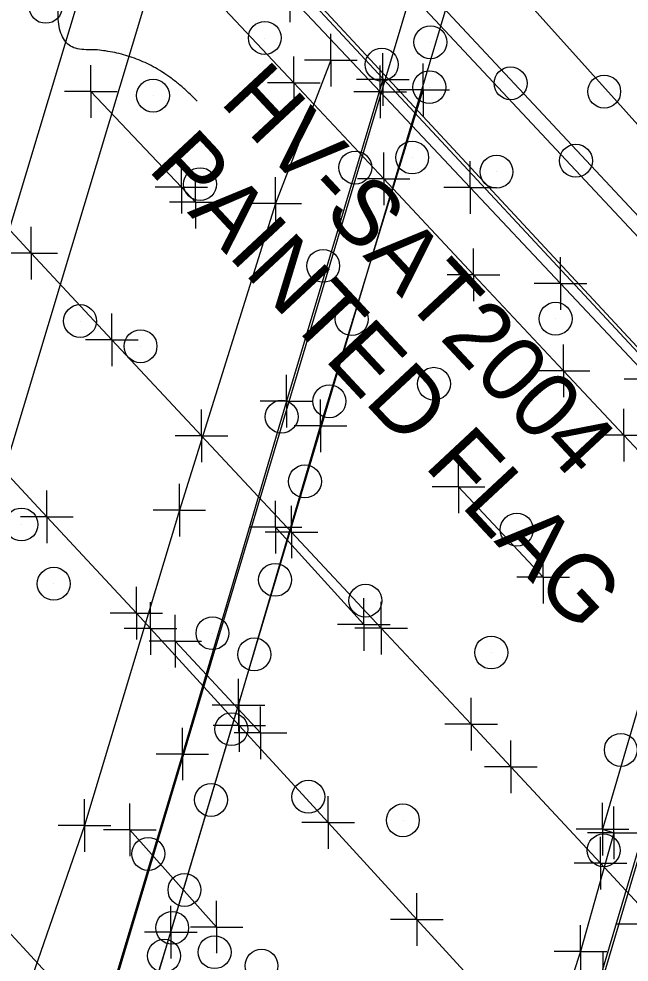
# Model space of a CAD drawing. Extents: x 0 to 1944463, y 0 to 420651.
# Drawn here: x 1943164.5 to 1943210.9, y 417466.5 to 417538.1 of the extents above; entities that cross this region are included whole.
import ezdxf

# ---------------------------------------------------------------- set-up
doc = ezdxf.new("R2010")
doc.units = 0
for name, color, linetype in [('AERIAL - CTRL - Text', 7, 'Continuous'), ('SUR - DRG - Bridge Deck', 7, 'Continuous'), ('SUR - DRG - Bridges', 7, 'Continuous'), ('SUR - DTM - Breaklines', 7, 'Continuous'), ('SUR - DTM - Breaklines - Points - Locators', 7, 'Continuous'), ('SUR - DTM - Spot Points - Locators', 7, 'Continuous'), ('SUR - TR-CTRL - Pavement Marking', 7, 'Continuous'), ('SUR - TR-CTRL - Pavement Marking - Points - Locators', 7, 'Continuous'), ('SUR - TRAN - Features', 7, 'Continuous'), ('SUR - TRAN - Railroads', 7, 'Continuous'), ('SUR - VEG - Features', 7, 'Continuous')]:
    doc.layers.add(name, color=color, linetype=linetype)

msp = doc.modelspace()

# ---------------------------------------------------------------- linework, layer by layer
at = {"layer": 'AERIAL - CTRL - Text'}
msp.add_open_spline([(1943178.089, 417531.873), (1943174.395, 417535.811), (1943164.646, 417535.811), (1943171.644, 417552.023)], degree=2, dxfattribs=at)
at = {"layer": 'SUR - DRG - Bridge Deck'}
for points in [[(1943115.55, 417624.338), (1943152.054, 417585.354), (1943187.334, 417547.54), (1943222.006, 417510.484)], [(1943113.605, 417617.591), (1943147.37, 417581.35), (1943183.041, 417543.482), (1943220.131, 417503.654)], [(1943113.608, 417617.795), (1943147.49, 417581.399), (1943183.285, 417543.641), (1943220.171, 417503.952)]]:
    msp.add_lwpolyline(points, dxfattribs=at)
at = {"layer": 'SUR - DRG - Bridges'}
msp.add_line((1943166.44, 417446.69), (1943194.62, 417540.97), dxfattribs=at)
msp.add_lwpolyline([(1943194.586, 417417.65), (1943160.612, 417454.166), (1943126.96, 417490.097), (1943087.359, 417532.419), (1943088.24, 417533.281), (1943102.062, 417579.551), (1943115.41, 417624.415), (1943114.938, 417624.906), (1943115.852, 417625.619), (1943152.828, 417586.155), (1943187.702, 417548.755), (1943222.943, 417511.078), (1943222.064, 417510.2)], close=True, dxfattribs=at)
msp.add_lwpolyline([(1943166.44, 417446.69), (1943169.26, 417445.81), (1943197.39, 417540.17), (1943194.62, 417540.97)], dxfattribs=at)
at = {"layer": 'SUR - DTM - Breaklines'}
for points in [[(1943188.25, 417535), (1943184.04, 417524.1), (1943176.74, 417500.81), (1943169.52, 417476.85), (1943165.09, 417464.05)], [(1943192.22, 417533.53), (1943184.89, 417509.08), (1943176.97, 417482.28), (1943169.11, 417456.04), (1943165.69, 417446.3)], [(1943169.06, 417445.88), (1943170.3, 417449.24), (1943172.17, 417455.81), (1943173.54, 417460.42), (1943176.1, 417468.74), (1943181.24, 417486), (1943187.47, 417507.21), (1943195.29, 417532.75)], [(1943218.59, 417509.53), (1943215.96, 417501.29), (1943213.27, 417491.41), (1943208.92, 417476.57), (1943209.78, 417476.3), (1943207.25, 417467.28), (1943203.9, 417457.1), (1943201.6, 417449.06), (1943199.15, 417440.38), (1943194, 417424.62), (1943191.92, 417417.37)], [(1943197.33, 417425.5), (1943208.97, 417465.3), (1943220.33, 417503.55)]]:
    msp.add_lwpolyline(points, dxfattribs=at)
at = {"layer": 'SUR - DTM - Breaklines - Points - Locators'}
for p, q in [((1943188.25, 417535), (1943188.25, 417537)), ((1943192.22, 417533.53), (1943192.22, 417535.53)), ((1943188.25, 417535), (1943186.25, 417535)), ((1943188.25, 417535), (1943190.25, 417535)), ((1943188.25, 417535), (1943188.25, 417533)), ((1943195.29, 417532.75), (1943195.29, 417534.75)), ((1943192.22, 417533.53), (1943190.22, 417533.53)), ((1943192.22, 417533.53), (1943194.22, 417533.53)), ((1943192.22, 417533.53), (1943192.22, 417531.53)), ((1943195.29, 417532.75), (1943193.29, 417532.75)), ((1943195.29, 417532.75), (1943197.29, 417532.75)), ((1943195.29, 417532.75), (1943195.29, 417530.75)), ((1943184.04, 417524.1), (1943184.04, 417526.1)), ((1943184.04, 417524.1), (1943182.04, 417524.1)), ((1943184.04, 417524.1), (1943186.04, 417524.1)), ((1943184.04, 417524.1), (1943184.04, 417522.1)), ((1943184.89, 417509.08), (1943184.89, 417511.08)), ((1943184.89, 417509.08), (1943182.89, 417509.08)), ((1943184.89, 417509.08), (1943186.89, 417509.08)), ((1943184.89, 417509.08), (1943184.89, 417507.08)), ((1943187.47, 417507.21), (1943187.47, 417509.21)), ((1943187.47, 417507.21), (1943185.47, 417507.21)), ((1943187.47, 417507.21), (1943189.47, 417507.21)), ((1943187.47, 417507.21), (1943187.47, 417505.21)), ((1943176.74, 417500.81), (1943176.74, 417502.81)), ((1943176.74, 417500.81), (1943174.74, 417500.81)), ((1943176.74, 417500.81), (1943178.74, 417500.81)), ((1943176.74, 417500.81), (1943176.74, 417498.81)), ((1943181.24, 417486), (1943181.24, 417488)), ((1943181.24, 417486), (1943179.24, 417486)), ((1943181.24, 417486), (1943183.24, 417486)), ((1943181.24, 417486), (1943181.24, 417484)), ((1943176.97, 417482.28), (1943176.97, 417484.28)), ((1943176.97, 417482.28), (1943174.97, 417482.28)), ((1943176.97, 417482.28), (1943178.97, 417482.28)), ((1943176.97, 417482.28), (1943176.97, 417480.28)), ((1943169.52, 417476.85), (1943169.52, 417478.85)), ((1943208.92, 417476.57), (1943208.92, 417478.57)), ((1943209.78, 417476.3), (1943209.78, 417478.3)), ((1943169.52, 417476.85), (1943167.52, 417476.85)), ((1943169.52, 417476.85), (1943171.52, 417476.85)), ((1943169.52, 417476.85), (1943169.52, 417474.85)), ((1943208.92, 417476.57), (1943206.92, 417476.57)), ((1943208.92, 417476.57), (1943210.92, 417476.57)), ((1943208.92, 417476.57), (1943208.92, 417474.57)), ((1943209.78, 417476.3), (1943207.78, 417476.3)), ((1943209.78, 417476.3), (1943211.78, 417476.3)), ((1943209.78, 417476.3), (1943209.78, 417474.3)), ((1943176.1, 417468.74), (1943176.1, 417470.74)), ((1943207.25, 417467.28), (1943207.25, 417469.28)), ((1943176.1, 417468.74), (1943174.1, 417468.74)), ((1943176.1, 417468.74), (1943178.1, 417468.74)), ((1943176.1, 417468.74), (1943176.1, 417466.74)), ((1943207.25, 417467.28), (1943205.25, 417467.28)), ((1943207.25, 417467.28), (1943209.25, 417467.28)), ((1943207.25, 417467.28), (1943207.25, 417465.28)), ((1943208.97, 417465.3), (1943208.97, 417467.3))]:
    msp.add_line(p, q, dxfattribs=at)
at = {"layer": 'SUR - DTM - Spot Points - Locators'}
for p, q in [((1943183.25, 417536.68), (1943183.25, 417536.68)), ((1943195.84, 417536.35), (1943195.84, 417536.35)), ((1943192.14, 417534.65), (1943192.14, 417534.65)), ((1943201.94, 417533.23), (1943201.94, 417533.23)), ((1943174.75, 417532.3), (1943174.75, 417532.3)), ((1943195.76, 417532.94), (1943195.76, 417532.94)), ((1943209.06, 417532.6), (1943209.06, 417532.6)), ((1943194.46, 417527.59), (1943194.46, 417527.59)), ((1943206.91, 417527.35), (1943206.91, 417527.35)), ((1943190.13, 417526.83), (1943190.13, 417526.83)), ((1943200.87, 417526.51), (1943200.87, 417526.51)), ((1943178.33, 417525.57), (1943178.33, 417525.57)), ((1943187.69, 417519.36), (1943187.69, 417519.36)), ((1943169.2, 417515.17), (1943169.2, 417515.17)), ((1943189.86, 417515.31), (1943189.86, 417515.31)), ((1943205.36, 417515.34), (1943205.36, 417515.34)), ((1943173.8, 417513.25), (1943173.8, 417513.25)), ((1943196.11, 417510.4), (1943196.11, 417510.4)), ((1943188.16, 417509.07), (1943188.16, 417509.07)), ((1943184.53, 417507.9), (1943184.53, 417507.9)), ((1943186.3, 417502.98), (1943186.3, 417502.98)), ((1943164.74, 417499.71), (1943164.74, 417499.71)), ((1943202.41, 417499.32), (1943202.41, 417499.32)), ((1943167.2, 417495.21), (1943167.2, 417495.21)), ((1943184.03, 417495.5), (1943184.03, 417495.5)), ((1943190.9, 417493.92), (1943190.9, 417493.92)), ((1943179.27, 417491.45), (1943179.27, 417491.45)), ((1943200.47, 417489.98), (1943200.47, 417489.98)), ((1943182.45, 417489.84), (1943182.45, 417489.84)), ((1943180.71, 417484.16), (1943180.71, 417484.16)), ((1943210.32, 417482.58), (1943210.32, 417482.58)), ((1943179.16, 417478.78), (1943179.16, 417478.78)), ((1943186.56, 417479.02), (1943186.56, 417479.02)), ((1943193.75, 417477.23), (1943193.75, 417477.23)), ((1943209.01, 417474.95), (1943209.01, 417474.95)), ((1943174.39, 417474.68), (1943174.39, 417474.68)), ((1943177.14, 417471.94), (1943177.14, 417471.94)), ((1943176.21, 417469.06), (1943176.21, 417469.06)), ((1943179.43, 417467.21), (1943179.43, 417467.21)), ((1943175.59, 417466.94), (1943175.59, 417466.94))]:
    msp.add_line(p, q, dxfattribs=at)
for centre in [(1943166.579, 417539.051), (1943183.239, 417536.691), (1943195.829, 417536.361), (1943192.129, 417534.661), (1943201.929, 417533.241), (1943195.749, 417532.951), (1943209.049, 417532.611), (1943174.739, 417532.311), (1943194.449, 417527.601), (1943190.119, 417526.841), (1943206.899, 417527.361), (1943200.859, 417526.521), (1943178.319, 417525.581), (1943187.679, 417519.371), (1943189.849, 417515.321), (1943205.349, 417515.351), (1943169.189, 417515.181), (1943173.789, 417513.261), (1943196.099, 417510.411), (1943188.149, 417509.081), (1943184.519, 417507.911), (1943186.289, 417502.991), (1943164.729, 417499.721), (1943202.399, 417499.331), (1943167.189, 417495.221), (1943184.019, 417495.511), (1943190.889, 417493.931), (1943179.259, 417491.461), (1943182.439, 417489.851), (1943200.459, 417489.991), (1943180.699, 417484.171), (1943210.309, 417482.591), (1943179.149, 417478.791), (1943186.549, 417479.031), (1943193.739, 417477.241), (1943174.379, 417474.691), (1943208.999, 417474.961), (1943177.129, 417471.951), (1943176.199, 417469.071), (1943179.419, 417467.221), (1943175.579, 417466.951), (1943182.989, 417466.191)]:
    msp.add_circle(centre, 1.25, dxfattribs=at)
at = {"layer": 'SUR - TR-CTRL - Pavement Marking'}
for points in [[(1943098.42, 417635.279), (1943103.018, 417629.276), (1943109.491, 417621.654), (1943112.594, 417618), (1943119.388, 417610.663), (1943126.183, 417603.326), (1943132.978, 417595.989), (1943138.955, 417589.534), (1943145.75, 417582.197), (1943152.545, 417574.86), (1943159.34, 417567.523), (1943166.134, 417560.186), (1943171.446, 417554.451), (1943178.3, 417547.169), (1943185.154, 417539.887), (1943192.008, 417532.606), (1943198.862, 417525.324), (1943205.716, 417518.042), (1943212.57, 417510.76)], [(1943109.726, 417614.439), (1943116.557, 417607.135), (1943123.387, 417599.832), (1943130.218, 417592.529), (1943137.049, 417585.225), (1943142.549, 417579.345), (1943149.353, 417572.016), (1943156.157, 417564.688), (1943162.961, 417557.359), (1943169.765, 417550.031), (1943171.766, 417547.876), (1943178.604, 417540.579), (1943185.442, 417533.282), (1943192.28, 417525.986), (1943199.118, 417518.689), (1943205.956, 417511.392), (1943210.536, 417506.506), (1943217.374, 417499.209)], [(1943049.034, 417591.82), (1943055.909, 417584.558), (1943062.785, 417577.297), (1943067.272, 417572.558), (1943074.12, 417565.271), (1943080.969, 417557.985), (1943087.818, 417550.698), (1943089.003, 417549.436), (1943095.803, 417542.105), (1943102.604, 417534.773), (1943109.404, 417527.441), (1943116.204, 417520.109), (1943117.838, 417518.348), (1943124.638, 417511.016), (1943131.439, 417503.684), (1943138.239, 417496.352), (1943145.039, 417489.02), (1943147.729, 417486.12), (1943154.51, 417478.77), (1943161.291, 417471.42), (1943168.072, 417464.071)], [(1943109.208, 417580.822), (1943116.02, 417573.5), (1943122.831, 417566.179), (1943129.643, 417558.857), (1943136.454, 417551.536), (1943138.234, 417549.623), (1943145.045, 417542.301), (1943151.857, 417534.98), (1943158.668, 417527.659), (1943165.48, 417520.337), (1943171.602, 417513.757), (1943178.432, 417506.453), (1943185.262, 417499.149), (1943192.092, 417491.844), (1943198.922, 417484.54), (1943201.947, 417481.305), (1943208.757, 417473.982), (1943215.567, 417466.659)], [(1943092.328, 417580.219), (1943099.155, 417572.913), (1943105.446, 417566.18), (1943112.254, 417558.855), (1943119.061, 417551.53), (1943125.869, 417544.204), (1943132.676, 417536.879), (1943139.483, 417529.554), (1943146.241, 417522.283), (1943153.048, 417514.958), (1943159.856, 417507.633), (1943166.663, 417500.307), (1943173.47, 417492.982), (1943174.548, 417491.823), (1943181.301, 417484.447), (1943188.054, 417477.072), (1943194.807, 417469.696), (1943199.772, 417464.274)], [(1943170.02, 417532.617), (1943176.893, 417525.354), (1943177.981, 417524.205)], [(1943197.974, 417502.571), (1943204.403, 417495.722)], [(1943184.064, 417499.513), (1943190.778, 417492.129)], [(1943176.433, 417490.854), (1943182.909, 417483.879)], [(1943172.97, 417476.519), (1943179.577, 417469.135)]]:
    msp.add_lwpolyline(points, dxfattribs=at)
at = {"layer": 'SUR - TR-CTRL - Pavement Marking - Points - Locators'}
for p, q in [((1943185.154, 417539.887), (1943185.154, 417537.887)), ((1943170.02, 417532.617), (1943170.02, 417534.617)), ((1943192.008, 417532.606), (1943192.008, 417534.606)), ((1943170.02, 417532.617), (1943168.02, 417532.617)), ((1943170.02, 417532.617), (1943172.02, 417532.617)), ((1943170.02, 417532.617), (1943170.02, 417530.617)), ((1943192.008, 417532.606), (1943190.008, 417532.606)), ((1943192.008, 417532.606), (1943194.008, 417532.606)), ((1943192.008, 417532.606), (1943192.008, 417530.606)), ((1943176.893, 417525.354), (1943176.893, 417527.354)), ((1943198.862, 417525.324), (1943198.862, 417527.324)), ((1943177.981, 417524.205), (1943177.981, 417526.205)), ((1943176.893, 417525.354), (1943174.893, 417525.354)), ((1943176.893, 417525.354), (1943178.893, 417525.354)), ((1943176.893, 417525.354), (1943176.893, 417523.354)), ((1943198.862, 417525.324), (1943196.862, 417525.324)), ((1943198.862, 417525.324), (1943200.862, 417525.324)), ((1943198.862, 417525.324), (1943198.862, 417523.324)), ((1943177.981, 417524.205), (1943175.981, 417524.205)), ((1943177.981, 417524.205), (1943179.981, 417524.205)), ((1943177.981, 417524.205), (1943177.981, 417522.205)), ((1943165.48, 417520.337), (1943165.48, 417522.337)), ((1943165.48, 417520.337), (1943163.48, 417520.337)), ((1943165.48, 417520.337), (1943167.48, 417520.337)), ((1943165.48, 417520.337), (1943165.48, 417518.337)), ((1943205.716, 417518.042), (1943205.716, 417520.042)), ((1943205.716, 417518.042), (1943203.716, 417518.042)), ((1943205.716, 417518.042), (1943207.716, 417518.042)), ((1943205.716, 417518.042), (1943205.716, 417516.042)), ((1943171.602, 417513.757), (1943171.602, 417515.757)), ((1943171.602, 417513.757), (1943169.602, 417513.757)), ((1943171.602, 417513.757), (1943173.602, 417513.757)), ((1943171.602, 417513.757), (1943171.602, 417511.757)), ((1943212.57, 417510.76), (1943210.57, 417510.76)), ((1943178.432, 417506.453), (1943178.432, 417508.453)), ((1943178.432, 417506.453), (1943176.432, 417506.453)), ((1943178.432, 417506.453), (1943180.432, 417506.453)), ((1943178.432, 417506.453), (1943178.432, 417504.453)), ((1943197.974, 417502.571), (1943197.974, 417504.571)), ((1943166.663, 417500.307), (1943166.663, 417502.307)), ((1943197.974, 417502.571), (1943195.974, 417502.571)), ((1943197.974, 417502.571), (1943199.974, 417502.571)), ((1943197.974, 417502.571), (1943197.974, 417500.571)), ((1943184.064, 417499.513), (1943184.064, 417501.513)), ((1943185.262, 417499.149), (1943185.262, 417501.149)), ((1943166.663, 417500.307), (1943164.663, 417500.307)), ((1943166.663, 417500.307), (1943168.663, 417500.307)), ((1943166.663, 417500.307), (1943166.663, 417498.307)), ((1943184.064, 417499.513), (1943182.064, 417499.513)), ((1943184.064, 417499.513), (1943186.064, 417499.513)), ((1943184.064, 417499.513), (1943184.064, 417497.513)), ((1943185.262, 417499.149), (1943183.262, 417499.149)), ((1943185.262, 417499.149), (1943187.262, 417499.149)), ((1943185.262, 417499.149), (1943185.262, 417497.149)), ((1943204.403, 417495.722), (1943204.403, 417497.722)), ((1943204.403, 417495.722), (1943202.403, 417495.722)), ((1943204.403, 417495.722), (1943206.403, 417495.722)), ((1943204.403, 417495.722), (1943204.403, 417493.722)), ((1943173.47, 417492.982), (1943173.47, 417494.982)), ((1943174.548, 417491.823), (1943174.548, 417493.823)), ((1943190.778, 417492.129), (1943190.778, 417494.129)), ((1943192.092, 417491.844), (1943192.092, 417493.844)), ((1943173.47, 417492.982), (1943171.47, 417492.982)), ((1943173.47, 417492.982), (1943175.47, 417492.982)), ((1943173.47, 417492.982), (1943173.47, 417490.982)), ((1943176.433, 417490.854), (1943176.433, 417492.854)), ((1943190.778, 417492.129), (1943188.778, 417492.129)), ((1943190.778, 417492.129), (1943192.778, 417492.129)), ((1943190.778, 417492.129), (1943190.778, 417490.129)), ((1943174.548, 417491.823), (1943172.548, 417491.823)), ((1943174.548, 417491.823), (1943176.548, 417491.823)), ((1943174.548, 417491.823), (1943174.548, 417489.823)), ((1943192.092, 417491.844), (1943190.092, 417491.844)), ((1943192.092, 417491.844), (1943194.092, 417491.844)), ((1943192.092, 417491.844), (1943192.092, 417489.844)), ((1943176.433, 417490.854), (1943174.433, 417490.854)), ((1943176.433, 417490.854), (1943178.433, 417490.854)), ((1943176.433, 417490.854), (1943176.433, 417488.854)), ((1943181.301, 417484.447), (1943181.301, 417486.447)), ((1943198.922, 417484.54), (1943198.922, 417486.54)), ((1943182.909, 417483.879), (1943182.909, 417485.879)), ((1943181.301, 417484.447), (1943179.301, 417484.447)), ((1943181.301, 417484.447), (1943183.301, 417484.447)), ((1943181.301, 417484.447), (1943181.301, 417482.447)), ((1943198.922, 417484.54), (1943196.922, 417484.54)), ((1943198.922, 417484.54), (1943200.922, 417484.54)), ((1943198.922, 417484.54), (1943198.922, 417482.54)), ((1943182.909, 417483.879), (1943180.909, 417483.879)), ((1943182.909, 417483.879), (1943184.909, 417483.879)), ((1943182.909, 417483.879), (1943182.909, 417481.879)), ((1943201.947, 417481.305), (1943201.947, 417483.305)), ((1943201.947, 417481.305), (1943199.947, 417481.305)), ((1943201.947, 417481.305), (1943203.947, 417481.305)), ((1943201.947, 417481.305), (1943201.947, 417479.305)), ((1943172.97, 417476.519), (1943172.97, 417478.519)), ((1943188.054, 417477.072), (1943188.054, 417479.072)), ((1943188.054, 417477.072), (1943186.054, 417477.072)), ((1943188.054, 417477.072), (1943190.054, 417477.072)), ((1943188.054, 417477.072), (1943188.054, 417475.072)), ((1943172.97, 417476.519), (1943170.97, 417476.519)), ((1943172.97, 417476.519), (1943174.97, 417476.519)), ((1943172.97, 417476.519), (1943172.97, 417474.519)), ((1943208.757, 417473.982), (1943208.757, 417475.982)), ((1943208.757, 417473.982), (1943206.757, 417473.982)), ((1943208.757, 417473.982), (1943210.757, 417473.982)), ((1943208.757, 417473.982), (1943208.757, 417471.982)), ((1943194.807, 417469.696), (1943194.807, 417471.696)), ((1943179.577, 417469.135), (1943179.577, 417471.135)), ((1943194.807, 417469.696), (1943192.807, 417469.696)), ((1943194.807, 417469.696), (1943196.807, 417469.696)), ((1943194.807, 417469.696), (1943194.807, 417467.696)), ((1943211.927, 417469.354), (1943209.927, 417469.354)), ((1943179.577, 417469.135), (1943177.577, 417469.135)), ((1943179.577, 417469.135), (1943181.577, 417469.135)), ((1943179.577, 417469.135), (1943179.577, 417467.135))]:
    msp.add_line(p, q, dxfattribs=at)
at = {"layer": 'SUR - TRAN - Features'}
for p, q in [((1943185.442, 417533.282), (1943185.442, 417535.282)), ((1943185.442, 417533.282), (1943183.442, 417533.282)), ((1943185.442, 417533.282), (1943187.442, 417533.282)), ((1943185.442, 417533.282), (1943185.442, 417531.282)), ((1943192.28, 417525.986), (1943192.28, 417527.986)), ((1943192.28, 417525.986), (1943190.28, 417525.986)), ((1943192.28, 417525.986), (1943194.28, 417525.986)), ((1943192.28, 417525.986), (1943192.28, 417523.986)), ((1943199.118, 417518.689), (1943199.118, 417520.689)), ((1943199.118, 417518.689), (1943197.118, 417518.689)), ((1943199.118, 417518.689), (1943201.118, 417518.689)), ((1943199.118, 417518.689), (1943199.118, 417516.689)), ((1943205.956, 417511.392), (1943205.956, 417513.392)), ((1943205.956, 417511.392), (1943203.956, 417511.392)), ((1943205.956, 417511.392), (1943207.956, 417511.392)), ((1943205.956, 417511.392), (1943205.956, 417509.392)), ((1943210.536, 417506.506), (1943210.536, 417508.506)), ((1943210.536, 417506.506), (1943208.536, 417506.506)), ((1943210.536, 417506.506), (1943212.536, 417506.506)), ((1943210.536, 417506.506), (1943210.536, 417504.506))]:
    msp.add_line(p, q, dxfattribs=at)
at = {"layer": 'SUR - TRAN - Railroads'}
for points in [[(1943093.8, 417289.09), (1943099.68, 417308.96), (1943109.47, 417341.69), (1943118.91, 417373.09), (1943128.73, 417405.59), (1943143.71, 417455.42), (1943175.9, 417562.25), (1943188.11, 417602.58), (1943216.37, 417696.61), (1943236.5, 417763.05)], [(1943098.53, 417287.57), (1943104.56, 417307.63), (1943114.3, 417340.28), (1943123.75, 417371.73), (1943133.57, 417404.59), (1943148.36, 417453.81), (1943180.54, 417560.57), (1943192.93, 417601.39), (1943221.1, 417695.23), (1943241.09, 417761.6)]]:
    msp.add_lwpolyline(points, dxfattribs=at)
at = {"layer": 'SUR - VEG - Features'}
msp.add_lwpolyline([(1943235.464, 417576.799), (1943289.083, 417568.714), (1943287.338, 417557.135), (1943262.641, 417548.503), (1943254.151, 417482.811), (1943195.339, 417548.192), (1943249.23, 417727.998)], dxfattribs=at)

# ---------------------------------------------------------------- texts
at = {"layer": 'AERIAL - CTRL - Text'}
for s, height, p in [('HV-SAT2004', 5, (1943179.745, 417531.809)), ('PAINTED FLAG', 4.99999, (1943174.26, 417526.694))]:
    msp.add_text(s, height=height, rotation=313, dxfattribs=at).set_placement(p)

doc.saveas('drawing.dxf')
